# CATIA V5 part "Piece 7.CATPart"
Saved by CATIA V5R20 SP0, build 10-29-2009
Part number: Piece 7
Bounding box of the stored display mesh (mm): x -80.022 to 84.44, y -29.343 to -12.461, z 0 to 2
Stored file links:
  G:\Khaled_CFAO_2011\SIL\SIL_GR1\blaboucarri\Khaled\CAD_CATIA\Piece 7.CATPart
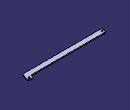
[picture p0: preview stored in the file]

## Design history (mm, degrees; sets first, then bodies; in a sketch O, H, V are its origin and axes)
Parameters
  `grande longueur` = 160 mm
  `petite longueur` = 15 mm
  largeur = 10 mm
  `épaisseur` = 2 mm
  `rayon trou ` = 1.5 mm
  `distance trou bord` = 2 mm
  `déviation` = 110 deg
Body1 (main body)
  Sketch1 on xy-plane, origin (0, 0, 0), H (1, 0, 0), V (0, 1, 0)
    point P1 (-80.0221, -29.343)
    line L1 (-77.4506, -29.343) -> (78.0872, -29.343)
    point P2 (79.9779, -29.343)
    line L2 (80.6246, -27.5663) -> (84.2966, -17.4776)
    point P3 (85.1082, -15.2476)
    line L3 (82.8782, -14.4359) -> (77.826, -12.5971)
    point P4 (75.7113, -11.8274)
    line L4 (74.9416, -13.9421) -> (73.5569, -17.7467)
    line L5 (71.2771, -19.343) -> (-76.8561, -19.343)
    point P5 (-80.0221, -19.343)
    line L6 (-80.0221, -22.5089) -> (-80.0221, -26.7715)
    circle A1 centre (-76.5221, -24.343) radius 1.5
    point P6 (-76.5221, -24.343)
    circle A2 centre (79.2127, -16.8264) radius 1.5
    point P7 (79.2127, -16.8264)
    arc A3 centre (77.0563, -14.7118) radius 2.2505 from (77.826, -12.5971) to (74.9416, -13.9421) ccw
    arc A4 centre (82.0665, -16.6659) radius 2.3731 from (82.8782, -14.4359) to (84.2966, -17.4776) cw
    arc A5 centre (71.2771, -16.9169) radius 2.426 from (73.5569, -17.7467) to (71.2771, -19.343) cw
    arc A6 centre (78.0872, -26.6428) radius 2.7002 from (80.6246, -27.5663) to (78.0872, -29.343) cw
    arc A7 centre (-76.8561, -22.5089) radius 3.1659 from (-76.8561, -19.343) to (-80.0221, -22.5089) ccw
    arc A8 centre (-77.4506, -26.7715) radius 2.5715 from (-80.0221, -26.7715) to (-77.4506, -29.343) ccw
    angle L4 L5 = 110 {= `déviation`}
    radius A2 = 1.5 {= `rayon trou `}
    radius A1 = 1.5 {= `rayon trou `}
    distance P6 L6 = 3.5 {= `distance trou bord` +`rayon trou `}
    distance P6 L1 = 5 {= largeur /2}
    distance P7 L3 = 3.5 {= `distance trou bord` +`rayon trou `}
    distance P7 L2 = 5 {= largeur /2}
    distance P3 P4 = 10 {= largeur}
    radius A3 = 2.2505
    distance P2 P3 = 15 {= `petite longueur`}
    radius A4 = 2.3731
    radius A5 = 2.426
    distance P1 P2 = 160 {= `grande longueur`}
    radius A6 = 2.7002
    distance P5 P1 = 10 {= largeur}
    radius A7 = 3.1659
    radius A8 = 2.5715
    horizontal: L1 H, L5 H
    perpendicularity: L3 L2
    parallelism: L4 L2
    vertical: L6 V
    coincidence: L3 P4, L4 P4, L3 P3, L2 P3, L2 P2, L1 P2, L5 P5, L6 P5, L6 P1, L1 P1
    tangency: A3 L3, A3 L4, A4 L3, A4 L2, A5 L4, A5 L5, A6 L2, A6 L1, A7 L5, A7 L6, A8 L6, A8 L1
  Pad1: profile Sketch1, direction (0, 0, 1), length 2 {= `épaisseur`}
Relations
  Sketch1.distance(P3 P4) = largeur `épaisseur` (deactivated)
